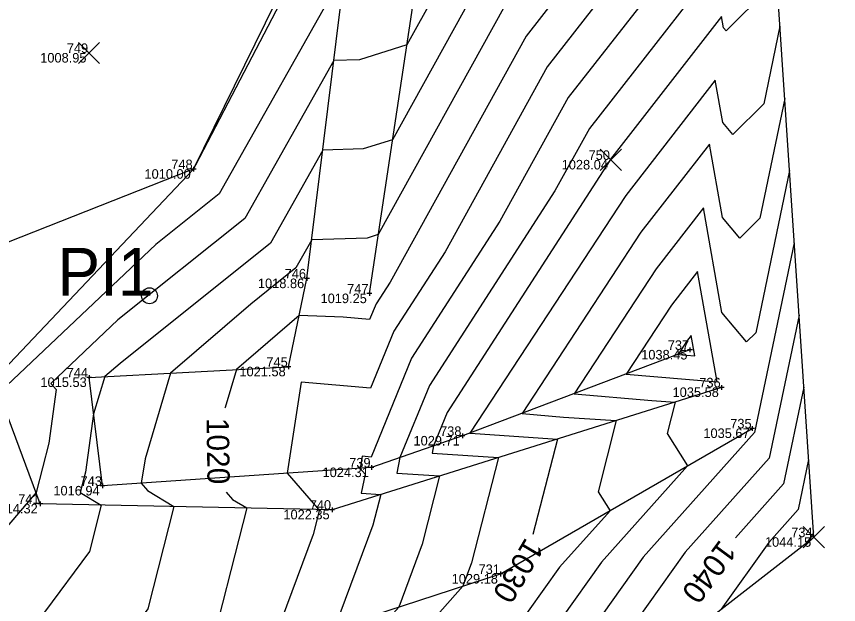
# Model space of a CAD drawing. Extents: x 2354693 to 2355622, y 637071 to 710080.
# Drawn here: x 2355430.4 to 2355533.4, y 709213 to 709286.7 of the extents above; entities that cross this region are included whole.
import ezdxf

# ---------------------------------------------------------------- set-up
doc = ezdxf.new("R2010")
doc.units = 0
for name, color, linetype in [('Default', 7, 'Continuous'), ('DT_X_Contour_Major', 7, 'Continuous'), ('DT_X_Contour_Minor', 7, 'Continuous'), ('PM_X_Surveyed_Line', 7, 'Continuous'), ('SV_X_Break_Lines', 7, 'Continuous'), ('SV_X_Random_Point', 7, 'Continuous'), ('SV_X_Shot_Marker', 7, 'Continuous'), ('SV_X_Text_Elevation', 7, 'Continuous'), ('SV_X_Text_Name', 7, 'Continuous'), ('SV_X_Toe_of_Slope', 7, 'Continuous'), ('SV_X_Top_of_Bank', 7, 'Continuous')]:
    doc.layers.add(name, color=color, linetype=linetype)

msp = doc.modelspace()

# ---------------------------------------------------------------- linework, layer by layer
at = {"layer": 'Default'}
msp.add_lwpolyline([(2355263.76, 708986.4), (2355330.91, 709003.61), (2355347.35, 709002.09), (2355387.45, 709051.54), (2355402.1, 709089.16), (2355425.96, 709130.16), (2355495.56, 709194.41), (2355530.33, 709221.46), (2355525, 709302.12), (2355509.66, 709318.33), (2355534.8, 709413.26), (2355566.11, 709428.47), (2355585.74, 709473.78), (2355589.64, 709532.44), (2355608.23, 709591.27)], dxfattribs=at)
msp.add_lwpolyline([(2355263.76, 708986.4), (2355330.91, 709003.61), (2355347.35, 709002.09), (2355387.45, 709051.54), (2355402.1, 709089.16), (2355425.96, 709130.16), (2355495.56, 709194.41), (2355530.33, 709221.46), (2355525, 709302.12), (2355509.66, 709318.33), (2355534.8, 709413.26), (2355566.11, 709428.47), (2355585.74, 709473.78), (2355589.64, 709532.44), (2355608.23, 709591.27)], dxfattribs=at)
msp.add_circle((2355447.08, 709251.71), 1, dxfattribs=at)
msp.add_circle((2355447.08, 709251.71), 1, dxfattribs=at)
msp.add_circle((2355447.08, 709251.71), 1, dxfattribs=at)
at = {"layer": 'DT_X_Contour_Major'}
for points in [[(2355515.17, 709312.51), (2355512.73, 709308.93), (2355502.73, 709295.09), (2355494.29, 709284.26), (2355477.23, 709253.42), (2355475.48, 709250.7), (2355474.67, 709248.74), (2355471.36, 709249.03), (2355465.85, 709249.25), (2355457.97, 709242.47), (2355456.56, 709237.73), (2355456.54, 709237.65)], [(2355515.17, 709312.51), (2355512.73, 709308.93), (2355502.73, 709295.09), (2355494.29, 709284.26), (2355477.23, 709253.42), (2355475.48, 709250.7), (2355474.67, 709248.74), (2355471.36, 709249.03), (2355465.85, 709249.25), (2355457.97, 709242.47), (2355456.56, 709237.73), (2355456.54, 709237.65)], [(2355466.95, 709295.19), (2355452.85, 709268.07), (2355452.66, 709267.73), (2355452.57, 709267.62), (2355452.2, 709267.46), (2355421.16, 709255.22), (2355416.53, 709254.8), (2355413.99, 709261.4), (2355405.36, 709273.14), (2355396.68, 709274.87)], [(2355466.95, 709295.19), (2355452.85, 709268.07), (2355452.66, 709267.73), (2355452.57, 709267.62), (2355452.2, 709267.46), (2355421.16, 709255.22), (2355416.53, 709254.8), (2355413.99, 709261.4), (2355405.36, 709273.14), (2355396.68, 709274.87)], [(2355526.1, 709285.5), (2355524.07, 709275.78), (2355520.2, 709271.92), (2355518.95, 709273.41), (2355518, 709278.73), (2355506.78, 709264.26), (2355487.24, 709234.51), (2355487.91, 709234.45), (2355498.2, 709233.76), (2355495.14, 709221.78)], [(2355526.1, 709285.5), (2355524.07, 709275.78), (2355520.2, 709271.92), (2355518.95, 709273.41), (2355518, 709278.73), (2355506.78, 709264.26), (2355487.24, 709234.51), (2355487.91, 709234.45), (2355498.2, 709233.76), (2355495.14, 709221.78)], [(2355529.09, 709240.25), (2355526.56, 709228.14), (2355520.54, 709221.4)], [(2355529.09, 709240.25), (2355526.56, 709228.14), (2355520.54, 709221.4)], [(2355456.69, 709227.11), (2355457.48, 709226.2), (2355459.26, 709225.12), (2355454.22, 709205.33), (2355454.08, 709205.14), (2355453.9, 709204.8), (2355453.96, 709204.72), (2355452.92, 709203.76), (2355421.91, 709177.07), (2355419.27, 709170.6), (2355416.05, 709165.77), (2355412.7, 709160.36), (2355405.68, 709150.4), (2355404.68, 709148.79)], [(2355456.69, 709227.11), (2355457.48, 709226.2), (2355459.26, 709225.12), (2355454.22, 709205.33), (2355454.08, 709205.14), (2355453.9, 709204.8), (2355453.96, 709204.72), (2355452.92, 709203.76), (2355421.91, 709177.07), (2355419.27, 709170.6), (2355416.05, 709165.77), (2355412.7, 709160.36), (2355405.68, 709150.4), (2355404.68, 709148.79)]]:
    msp.add_lwpolyline(points, dxfattribs=at)
at = {"layer": 'DT_X_Contour_Minor'}
for points in [[(2355511.72, 709354.01), (2355500.11, 709329.49), (2355487.86, 709305.34), (2355484.78, 709301.07), (2355483.71, 709299.69), (2355481.13, 709295.03), (2355472.96, 709292.48), (2355471.58, 709292.43), (2355455.81, 709264.49), (2355447.87, 709258.14), (2355428.41, 709239.73)], [(2355511.72, 709354.01), (2355500.11, 709329.49), (2355487.86, 709305.34), (2355484.78, 709301.07), (2355483.71, 709299.69), (2355481.13, 709295.03), (2355472.96, 709292.48), (2355471.58, 709292.43), (2355455.81, 709264.49), (2355447.87, 709258.14), (2355428.41, 709239.73)], [(2355510.79, 709337.99), (2355504.4, 709324.48), (2355497.65, 709311.17), (2355489.27, 709299.57), (2355486.35, 709295.83), (2355479.34, 709283.15), (2355473.42, 709281.3), (2355470.19, 709281.19), (2355459.02, 709261.4), (2355443.13, 709248.69), (2355434.71, 709240.72), (2355435.4, 709239.96), (2355434.45, 709233.23), (2355432.86, 709227.06), (2355429.2, 709222.75)], [(2355510.79, 709337.99), (2355504.4, 709324.48), (2355497.65, 709311.17), (2355489.27, 709299.57), (2355486.35, 709295.83), (2355479.34, 709283.15), (2355473.42, 709281.3), (2355470.19, 709281.19), (2355459.02, 709261.4), (2355443.13, 709248.69), (2355434.71, 709240.72), (2355435.4, 709239.96), (2355434.45, 709233.23), (2355432.86, 709227.06), (2355429.2, 709222.75)], [(2355510.91, 709323.07), (2355509.87, 709321.98), (2355508.68, 709319.47), (2355507.43, 709317), (2355493.75, 709298.08), (2355489, 709291.97), (2355477.54, 709271.27), (2355473.88, 709270.13), (2355468.81, 709269.95), (2355462.23, 709258.3), (2355443.4, 709243.24), (2355441.47, 709241.59), (2355440.08, 709236.93), (2355439.04, 709229.6), (2355438.39, 709227.08), (2355441.03, 709225.48), (2355439.54, 709219.65), (2355433.91, 709212.05), (2355427.03, 709199.09)], [(2355510.91, 709323.07), (2355509.87, 709321.98), (2355508.68, 709319.47), (2355507.43, 709317), (2355493.75, 709298.08), (2355489, 709291.97), (2355477.54, 709271.27), (2355473.88, 709270.13), (2355468.81, 709269.95), (2355462.23, 709258.3), (2355443.4, 709243.24), (2355441.47, 709241.59), (2355440.08, 709236.93), (2355439.04, 709229.6), (2355438.39, 709227.08), (2355441.03, 709225.48), (2355439.54, 709219.65), (2355433.91, 709212.05), (2355427.03, 709199.09)], [(2355512.06, 709315.8), (2355511, 709314.24), (2355498.24, 709296.58), (2355491.64, 709288.12), (2355475.75, 709259.39), (2355474.35, 709258.95), (2355467.42, 709258.71), (2355465.44, 709255.21), (2355459.78, 709250.68), (2355449.72, 709242.03), (2355446.52, 709231.3), (2355446.05, 709228.22), (2355446.84, 709227.3), (2355450.15, 709225.3), (2355446.88, 709212.49), (2355443.99, 709208.59), (2355440.46, 709201.95), (2355441.77, 709200.32), (2355421.1, 709181.12)], [(2355512.06, 709315.8), (2355511, 709314.24), (2355498.24, 709296.58), (2355491.64, 709288.12), (2355475.75, 709259.39), (2355474.35, 709258.95), (2355467.42, 709258.71), (2355465.44, 709255.21), (2355459.78, 709250.68), (2355449.72, 709242.03), (2355446.52, 709231.3), (2355446.05, 709228.22), (2355446.84, 709227.3), (2355450.15, 709225.3), (2355446.88, 709212.49), (2355443.99, 709208.59), (2355440.46, 709201.95), (2355441.77, 709200.32), (2355421.1, 709181.12)], [(2355518.27, 709309.23), (2355514.46, 709303.63), (2355507.21, 709293.59), (2355496.93, 709280.4), (2355484.12, 709257.23), (2355477.7, 709247.29), (2355474.77, 709240.12), (2355466.09, 709240.88), (2355464.34, 709229.47), (2355468.12, 709225.09), (2355468.38, 709224.93), (2355467.59, 709221.81), (2355462.23, 709207.44), (2355459.02, 709203.82), (2355455.82, 709201.52), (2355428.34, 709177.87)], [(2355518.27, 709309.23), (2355514.46, 709303.63), (2355507.21, 709293.59), (2355496.93, 709280.4), (2355484.12, 709257.23), (2355477.7, 709247.29), (2355474.77, 709240.12), (2355466.09, 709240.88), (2355464.34, 709229.47), (2355468.12, 709225.09), (2355468.38, 709224.93), (2355467.59, 709221.81), (2355462.23, 709207.44), (2355459.02, 709203.82), (2355455.82, 709201.52), (2355428.34, 709177.87)], [(2355521.38, 709305.94), (2355516.2, 709298.32), (2355511.7, 709292.09), (2355499.57, 709276.54), (2355491.01, 709261.05), (2355479.93, 709243.88), (2355474.87, 709231.51), (2355473.72, 709231.61), (2355473.49, 709230.09), (2355474.12, 709229.36), (2355473.63, 709226.98), (2355476.06, 709226.81), (2355475.08, 709222.95), (2355470.27, 709210.06), (2355463.67, 709202.62), (2355457.1, 709197.88), (2355434.77, 709178.67), (2355427.81, 709161.59)], [(2355521.38, 709305.94), (2355516.2, 709298.32), (2355511.7, 709292.09), (2355499.57, 709276.54), (2355491.01, 709261.05), (2355479.93, 709243.88), (2355474.87, 709231.51), (2355473.72, 709231.61), (2355473.49, 709230.09), (2355474.12, 709229.36), (2355473.63, 709226.98), (2355476.06, 709226.81), (2355475.08, 709222.95), (2355470.27, 709210.06), (2355463.67, 709202.62), (2355457.1, 709197.88), (2355434.77, 709178.67), (2355427.81, 709161.59)], [(2355524.49, 709302.66), (2355517.93, 709293.02), (2355516.18, 709290.6), (2355502.22, 709272.68), (2355497.89, 709264.86), (2355482.16, 709240.47), (2355478.46, 709231.43), (2355478.07, 709229.49), (2355483.44, 709229.13), (2355481.26, 709220.6), (2355478.31, 709212.69), (2355468.33, 709201.42), (2355458.38, 709194.25), (2355441.2, 709179.47), (2355435.74, 709166.06), (2355427.13, 709148.41)], [(2355524.49, 709302.66), (2355517.93, 709293.02), (2355516.18, 709290.6), (2355502.22, 709272.68), (2355497.89, 709264.86), (2355482.16, 709240.47), (2355478.46, 709231.43), (2355478.07, 709229.49), (2355483.44, 709229.13), (2355481.26, 709220.6), (2355478.31, 709212.69), (2355468.33, 709201.42), (2355458.38, 709194.25), (2355441.2, 709179.47), (2355435.74, 709166.06), (2355427.13, 709148.41)], [(2355525.5, 709294.55), (2355524.58, 709290.12), (2355519.34, 709284.91), (2355519.01, 709285.31), (2355518.76, 709286.73), (2355505.62, 709269.79), (2355504.86, 709268.82), (2355504.78, 709268.67), (2355484.39, 709237.07), (2355482.68, 709232.9), (2355482.5, 709232.01), (2355490.82, 709231.44), (2355487.45, 709218.24), (2355486.35, 709215.31), (2355472.99, 709200.22), (2355459.66, 709190.62), (2355447.63, 709180.27), (2355443.81, 709170.88), (2355426.26, 709134.89)], [(2355525.5, 709294.55), (2355524.58, 709290.12), (2355519.34, 709284.91), (2355519.01, 709285.31), (2355518.76, 709286.73), (2355505.62, 709269.79), (2355504.86, 709268.82), (2355504.78, 709268.67), (2355484.39, 709237.07), (2355482.68, 709232.9), (2355482.5, 709232.01), (2355490.82, 709231.44), (2355487.45, 709218.24), (2355486.35, 709215.31), (2355472.99, 709200.22), (2355459.66, 709190.62), (2355447.63, 709180.27), (2355443.81, 709170.88), (2355426.26, 709134.89)], [(2355526.7, 709276.45), (2355523.56, 709261.43), (2355521.06, 709258.93), (2355518.89, 709261.52), (2355517.25, 709270.73), (2355508.68, 709259.68), (2355493.77, 709236.98), (2355498.97, 709236.52), (2355505.58, 709236.08), (2355503.3, 709227.15), (2355504.8, 709224.78), (2355498.48, 709217.72), (2355492.57, 709209.42), (2355482.3, 709197.82), (2355462.22, 709183.35), (2355460.5, 709181.86), (2355459.95, 709180.52), (2355456.46, 709173.36), (2355451.49, 709153.73)], [(2355526.7, 709276.45), (2355523.56, 709261.43), (2355521.06, 709258.93), (2355518.89, 709261.52), (2355517.25, 709270.73), (2355508.68, 709259.68), (2355493.77, 709236.98), (2355498.97, 709236.52), (2355505.58, 709236.08), (2355503.3, 709227.15), (2355504.8, 709224.78), (2355498.48, 709217.72), (2355492.57, 709209.42), (2355482.3, 709197.82), (2355462.22, 709183.35), (2355460.5, 709181.86), (2355459.95, 709180.52), (2355456.46, 709173.36), (2355451.49, 709153.73)], [(2355527.3, 709267.4), (2355523.06, 709247.09), (2355521.92, 709245.95), (2355518.83, 709249.63), (2355516.5, 709262.74), (2355510.59, 709255.11), (2355500.29, 709239.44), (2355510.04, 709238.59), (2355512.96, 709238.39), (2355511.95, 709234.45), (2355514.51, 709230.4), (2355503.73, 709218.34), (2355493.62, 709204.15), (2355486.95, 709196.63), (2355471.36, 709185.38), (2355466.97, 709168.02)], [(2355527.3, 709267.4), (2355523.06, 709247.09), (2355521.92, 709245.95), (2355518.83, 709249.63), (2355516.5, 709262.74), (2355510.59, 709255.11), (2355500.29, 709239.44), (2355510.04, 709238.59), (2355512.96, 709238.39), (2355511.95, 709234.45), (2355514.51, 709230.4), (2355503.73, 709218.34), (2355493.62, 709204.15), (2355486.95, 709196.63), (2355471.36, 709185.38), (2355466.97, 709168.02)], [(2355527.89, 709258.35), (2355522.93, 709234.57), (2355508.97, 709218.95), (2355494.67, 709198.88), (2355491.61, 709195.43), (2355484.45, 709190.27), (2355482.44, 709182.3)], [(2355527.89, 709258.35), (2355522.93, 709234.57), (2355508.97, 709218.95), (2355494.67, 709198.88), (2355491.61, 709195.43), (2355484.45, 709190.27), (2355482.44, 709182.3)], [(2355515.75, 709254.74), (2355512.49, 709250.54), (2355506.82, 709241.91), (2355518.21, 709240.91), (2355515.75, 709254.74)], [(2355515.75, 709254.74), (2355512.49, 709250.54), (2355506.82, 709241.91), (2355518.21, 709240.91), (2355515.75, 709254.74)], [(2355528.49, 709249.3), (2355524.75, 709231.35), (2355514.21, 709219.57), (2355497.2, 709195.68)], [(2355528.49, 709249.3), (2355524.75, 709231.35), (2355514.21, 709219.57), (2355497.2, 709195.68)], [(2355514.99, 709246.74), (2355514.39, 709245.97), (2355513.34, 709244.37), (2355515.45, 709244.19), (2355514.99, 709246.74)], [(2355514.99, 709246.74), (2355514.39, 709245.97), (2355513.34, 709244.37), (2355515.45, 709244.19), (2355514.99, 709246.74)], [(2355529.69, 709231.2), (2355528.38, 709224.92), (2355524.69, 709220.8), (2355518.74, 709212.44)], [(2355529.69, 709231.2), (2355528.38, 709224.92), (2355524.69, 709220.8), (2355518.74, 709212.44)], [(2355530.29, 709222.15), (2355530.2, 709221.71), (2355529.93, 709221.41), (2355529.51, 709220.82)], [(2355530.29, 709222.15), (2355530.2, 709221.71), (2355529.93, 709221.41), (2355529.51, 709220.82)]]:
    msp.add_lwpolyline(points, dxfattribs=at)
at = {"layer": 'PM_X_Surveyed_Line'}
msp.add_line((2355447.08, 709251.71), (2355447.08, 709251.71), dxfattribs=at)
at = {"layer": 'SV_X_Break_Lines'}
msp.add_lwpolyline([(2355425.79, 709239.32), (2355452.61, 709267.58), (2355470.64, 709304.29)], dxfattribs=at)
at = {"layer": 'SV_X_Random_Point'}
for p, q in [((2355438.16, 709280.8), (2355440.82, 709283.47)), ((2355438.16, 709283.47), (2355440.82, 709280.8)), ((2355503.58, 709267.41), (2355506.25, 709270.08)), ((2355503.58, 709270.08), (2355506.25, 709267.41)), ((2355529, 709220.13), (2355531.67, 709222.8)), ((2355529, 709222.8), (2355531.67, 709220.13))]:
    msp.add_line(p, q, dxfattribs=at)
at = {"layer": 'SV_X_Shot_Marker'}
for p, q in [((2355452.91, 709267.58), (2355452.31, 709267.58)), ((2355452.61, 709267.88), (2355452.61, 709267.28)), ((2355466.82, 709254.18), (2355466.82, 709253.57)), ((2355467.12, 709253.88), (2355466.52, 709253.88)), ((2355474.94, 709251.99), (2355474.34, 709251.99)), ((2355474.64, 709252.29), (2355474.64, 709251.69)), ((2355515.12, 709244.93), (2355514.52, 709244.93)), ((2355514.82, 709245.23), (2355514.82, 709244.63)), ((2355464.79, 709242.82), (2355464.19, 709242.82)), ((2355464.49, 709243.12), (2355464.49, 709242.52)), ((2355439.52, 709241.78), (2355439.52, 709241.18)), ((2355439.82, 709241.48), (2355439.22, 709241.48)), ((2355518.79, 709240.53), (2355518.79, 709239.93)), ((2355519.09, 709240.23), (2355518.49, 709240.23)), ((2355522.63, 709235.39), (2355522.63, 709234.79)), ((2355486.29, 709234.45), (2355486.29, 709233.85)), ((2355522.93, 709235.09), (2355522.33, 709235.09)), ((2355486.59, 709234.15), (2355485.99, 709234.15)), ((2355475.19, 709230.19), (2355474.59, 709230.19)), ((2355474.89, 709230.49), (2355474.89, 709229.89)), ((2355441.2, 709228.19), (2355441.2, 709227.59)), ((2355441.5, 709227.89), (2355440.9, 709227.89)), ((2355433.69, 709225.64), (2355433.09, 709225.64)), ((2355433.39, 709225.94), (2355433.39, 709225.34)), ((2355469.97, 709225.2), (2355469.97, 709224.6)), ((2355470.27, 709224.9), (2355469.67, 709224.9)), ((2355491.39, 709216.85), (2355490.79, 709216.85)), ((2355491.09, 709217.15), (2355491.09, 709216.55))]:
    msp.add_line(p, q, dxfattribs=at)
at = {"layer": 'SV_X_Toe_of_Slope'}
for points in [[(2355474.64, 709251.99), (2355482.17, 709301.94), (2355491.1, 709340.03)], [(2355518.79, 709240.23), (2355469.97, 709224.9), (2355433.39, 709225.64), (2355428.95, 709237.57)], [(2355330.91, 709003.61), (2355357.29, 709054.66), (2355376.63, 709104.12), (2355386.68, 709149.19), (2355392.84, 709167.31), (2355399.71, 709185.13), (2355454.61, 709204.96), (2355491.09, 709216.85), (2355522.63, 709235.09)]]:
    msp.add_lwpolyline(points, dxfattribs=at)
at = {"layer": 'SV_X_Top_of_Bank'}
msp.add_lwpolyline([(2355514.82, 709244.93), (2355486.29, 709234.15), (2355474.89, 709230.19), (2355441.2, 709227.89), (2355439.52, 709241.48), (2355464.49, 709242.82), (2355466.82, 709253.88), (2355472.61, 709300.82)], dxfattribs=at)

# ---------------------------------------------------------------- texts
at = {"layer": 'DT_X_Contour_Major'}
for s, rotation, p in [('1020', 270.8233, (2355454.23, 709236.4)), ('1020', 270.8233, (2355454.23, 709236.4)), ('1030', 239.3461, (2355494.24, 709221.53)), ('1030', 239.3461, (2355494.24, 709221.53)), ('1040', 233.6165, (2355518.59, 709221.27)), ('1040', 233.6165, (2355518.59, 709221.27))]:
    msp.add_text(s, height=2.8, rotation=rotation, dxfattribs=at).set_placement(p)
at = {"layer": 'SV_X_Text_Elevation'}
for s, p in [('1008.95', (2355433.38, 709280.94)), ('1028.04', (2355498.74, 709267.54)), ('1010.00', (2355446.45, 709266.38)), ('1018.86', (2355460.67, 709252.67)), ('1019.25', (2355468.52, 709250.79)), ('1038.45', (2355508.71, 709243.73)), ('1021.58', (2355458.35, 709241.62)), ('1015.53', (2355433.41, 709240.28)), ('1035.58', (2355512.64, 709239.03)), ('1035.67', (2355516.5, 709233.89)), ('1029.71', (2355480.17, 709232.95)), ('1024.31', (2355468.77, 709228.99)), ('1016.94', (2355435.03, 709226.69)), ('1014.32', (2355427.27, 709224.44)), ('1022.35', (2355463.86, 709223.7)), ('1044.15', (2355524.22, 709220.26)), ('1029.18', (2355484.95, 709215.65))]:
    msp.add_text(s, height=1.2, dxfattribs=at).set_placement(p)
at = {"layer": 'SV_X_Text_Name'}
for s, height, p in [('749', 1.2, (2355436.71, 709282.14)), ('750', 1.2, (2355502.11, 709268.74)), ('748', 1.2, (2355449.81, 709267.58)), ('PI1', 6, (2355435.54, 709251.71)), ('746', 1.2, (2355464.02, 709253.88)), ('747', 1.2, (2355471.85, 709251.99)), ('737', 1.2, (2355512.04, 709244.93)), ('745', 1.2, (2355461.73, 709242.82)), ('744', 1.2, (2355436.7, 709241.48)), ('736', 1.2, (2355515.99, 709240.23)), ('738', 1.2, (2355483.5, 709234.15)), ('735', 1.2, (2355519.87, 709235.09)), ('739', 1.2, (2355472.11, 709230.19)), ('743', 1.2, (2355438.44, 709227.89)), ('741', 1.2, (2355430.62, 709225.64)), ('740', 1.2, (2355467.16, 709224.9)), ('734', 1.2, (2355527.51, 709221.46)), ('731', 1.2, (2355488.32, 709216.85))]:
    msp.add_text(s, height=height, dxfattribs=at).set_placement(p)

doc.saveas('drawing.dxf')
